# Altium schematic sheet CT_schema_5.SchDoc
size 297 x 271 mm
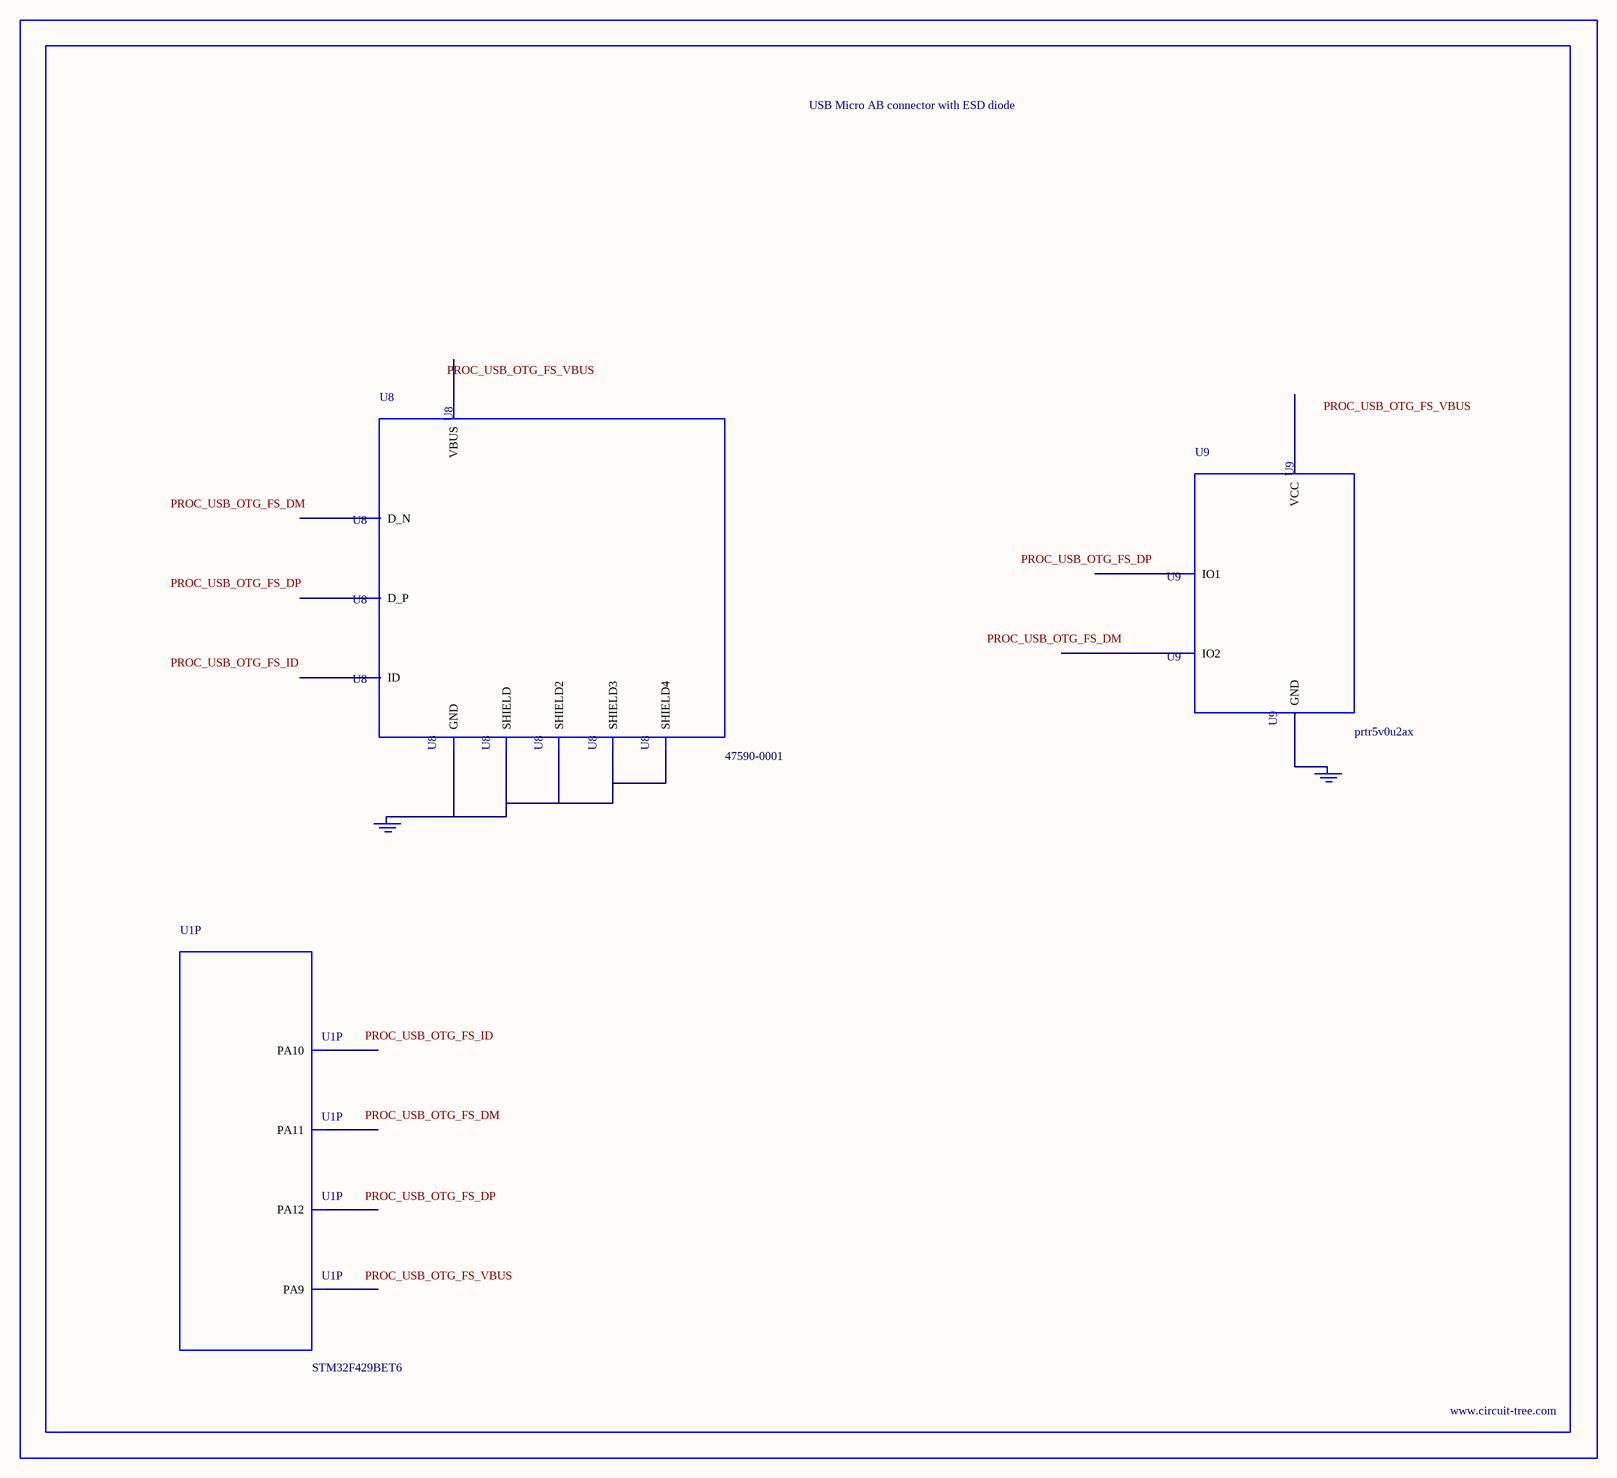
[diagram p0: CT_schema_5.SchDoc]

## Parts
BORDER4  (no value)
GND_INSTANCE_4_0  (no value)
GND_INSTANCE_4_1  (no value)
U1  STM32F429BET6  [LQFP208]  (part P of 16)
U8  47590-0001  [MICRO_USB_AB]
U9  prtr5v0u2ax  [SOT143B]

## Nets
NetGND_INSTANCE_4_0_0: GND_INSTANCE_4_0.0(GND) U8.5(GND) U8.6(SHIELD) U8.7(SHIELD2) U8.8(SHIELD3) U8.9(SHIELD4)
NetGND_INSTANCE_4_1_0: GND_INSTANCE_4_1.0(GND) U9.1(GND)

Not connected (* = marked no-connect by the designer): U1 143(PA9) 144(PA10) 145(PA11) 146(PA12); U8 1(VBUS) 2(D_N) 3(D_P) 4(ID); U9 2(IO1) 3(IO2) 4(VCC)

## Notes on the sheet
- Labels drawn without touching a wire or pin: PROC_USB_OTG_FS_DM, PROC_USB_OTG_FS_DP, PROC_USB_OTG_FS_ID, PROC_USB_OTG_FS_VBUS

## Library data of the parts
BORDER4 = BORDER_PAGE4
GND_INSTANCE_4_0 GND_INSTANCE_4_1 = GND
